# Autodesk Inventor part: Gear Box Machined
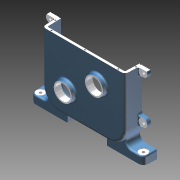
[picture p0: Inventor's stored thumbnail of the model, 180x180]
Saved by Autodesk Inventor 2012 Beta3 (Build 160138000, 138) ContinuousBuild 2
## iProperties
Created: 2008-05
Part Number: Gear Box Machined
Document SubType Name: Modeling
Designer: Thom Tremblay
Density: 2.71 g/cm^3
Material: Aluminum-6061
Mass: 2342.12 g
Surface Area: 1959.94 cm^2
Volume: 864.251 cm^3
Author: Thom Tremblay
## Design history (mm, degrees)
node "c8-12" dims "d0" = 10
workplane "Work Plane5"
split "Split4"
workplane "Work Plane1"
split "Split1"
workplane "Work Plane2"
split "Split2"
workplane "Work Plane3"
split "Split3"
sketch "Sketch2"
  geometry: L1 (-43.154, 195.566)-(-43.154, 43.154) reference; L2 (0, 0)-(152.426, 0) reference; L3 (195.579, 43.154)-(195.579, 195.566) reference; L4 (-44.932, 195.566)-(-44.932, 43.154); L5 (0, -1.778)-(152.426, -1.778); L6 (197.357, 43.154)-(197.357, 195.566); L7 (-48.107, 195.566)-(-48.107, 43.154); L8 (0, -4.953)-(152.426, -4.953); L9 (200.532, 43.154)-(200.532, 195.566); L10 (197.357, 195.566)-(200.532, 195.566); L11 (-48.107, 195.566)-(-44.932, 195.566); 2 further points; 2 other entities
  constraints: 16 end point, 8 parallel, 1 collinear, 1 perpendicular, 14 other
  dimensions: "d86" = 1.778 distance between parallel lines of L1 L4; "d87" = 3.175 distance of L7.start L4.start
extrude "Extrusion1" cut sketch "Sketch2" distance "d7" = 1.5875; taper "d8" = 0 deg
fillet "Fillet1" dims "d9" = 1.27
sketch "Sketch3"
  geometry: A1 r 12.342 centre (0, 9.804) between (-9.709, 17.424) and (0, -2.538) reference; A2 r 12.342 centre (0, -122.307) between (0, -109.965) and (0, -134.649) reference; A3 r 12.342 centre (99.06, -195.936) between (102.192, -207.874) and (111.402, -195.936) reference; A4 r 12.342 centre (185.42, -195.936) between (173.078, -195.936) and (182.288, -207.874) reference; A5 r 12.342 centre (284.48, -122.307) between (284.48, -134.649) and (284.48, -109.965) reference; A6 r 12.342 centre (284.48, 9.804) between (284.48, -2.538) and (294.189, 17.424) reference
hole "Hole4" sketch "Sketch3" at (0, 9.804), (0, -122.307), (99.06, -195.936), (185.42, -195.936), (284.48, -122.307), (284.48, 9.804) diameter "d37" = 8.4328; stored, may be unused: countersink angle "d41" = 82 deg, drill point angle "d43" = 118 deg; dims "d38" = 12.7, "d39" = 25.4, "d40" = 1.5875, "d42" = 19.05
sketch "Sketch4"
  geometry: L1 (-190.442, -18.372)-(-183.68, -30.3) reference; L2 (-255.6, 96.553)-(-248.837, 84.625) reference; L3 (-96.099, 8.151)-(-76.621, 8.151) reference; L4 (9.739, 8.151)-(-9.739, 8.151) reference; A1 r 12.7 centre (0, 0) between (9.739, 8.151) and (-9.739, 8.151) reference; A2 r 12.7 centre (-86.36, 0) between (-76.621, 8.151) and (-96.099, 8.151) reference; A3 r 12.7 centre (-196.361, -29.609) between (-183.68, -30.3) and (-190.442, -18.372) reference; A4 r 12.7 centre (-261.518, 85.317) between (-248.837, 84.625) and (-255.6, 96.553) reference
extrude "Extrusion2" cut sketch "Sketch4" stored distance "d44" = 1.5875; taper "d45" = 0 deg
workplane "Work Plane4"
hole "Hole5" diameter "d49" = 8.4328; stored, may be unused: countersink angle "d53" = 82 deg, drill point angle "d55" = 118 deg; dims "d47" = 25.4, "d48" = 25.4, "d50" = 12.7, "d51" = 25.4, "d52" = 1.5875, "d54" = 19.05
sketch "Sketch5"
  geometry: L1 (7.378, 0)-(0, 0) reference; A1 r 12.7 centre (0, -10.337) between (-12.382, -13.16) and (7.378, 0) reference; 2 further points; 1 other entity
  constraints: 2 other
extrude "Extrusion3" cut sketch "Sketch5" stored distance "d56" = 1.5875; taper "d57" = 0 deg
mirror "Mirror1"
hole "Hole6" diameter "d75" = 47; stored, may be unused: countersink angle "d79" = 82 deg, drill point angle "d81" = 118 deg; dims "d73" = 25.4, "d74" = 25.4, "d76" = 12.7, "d77" = 16.129, "d78" = 7.9502, "d80" = 19.05
chamfer "Chamfer2" distance "d82" = 1.27; stored, may be unused: second distance "d83" = 3.175, angle "d84" = 45 deg
sketch "Sketch7"
  geometry: L1 (233.368, 2.451)-(234.781, 42.926) reference; L2 (0, 0)-(230.829, 0) reference; L3 (-3.952, 42.926)-(-2.538, 2.451) reference; L4 (239.032, 55.493)-(237.175, 2.318); L5 (230.829, -3.81)-(0, -3.81); L6 (-6.346, 2.318)-(-8.203, 55.493); A1 r 2.54 centre (230.829, 2.54) between (230.829, 0) and (233.368, 2.451) reference; A2 r 2.54 centre (0, 2.54) between (-2.538, 2.451) and (0, 0) reference; A3 r 6.35 centre (230.829, 2.54) between (230.829, -3.81) and (237.175, 2.318); A4 r 6.35 centre (0, 2.54) between (-6.346, 2.318) and (0, -3.81); 5 further points
  constraints: 6 end point, 4 point on circle, 3 midpoint, 2 centre point, 2 point on line, 4 other
  dimensions: "d88" = 3.81 distance between parallel lines of L2 L5; "d89" = 101.6 distance of point (115.415, -3.81) point (217.015, -3.81); "d90" = 101.6 distance of point (13.815, -3.81) point (115.415, -3.81) (= d89)
hole "Hole8" sketch "Sketch7" at (115.415, -3.81), (217.015, -3.81), (13.815, -3.81), (-7.275, 28.906), (238.104, 28.906) diameter "d91" = 4.3434; stored, may be unused: countersink angle "d95" = 82 deg, drill point angle "d97" = 118 deg; dims "d92" = 8.89, "d93" = 16.129, "d94" = 7.9502, "d96" = 12.7
body "Solid1"
hole "Hole7" diameter "d66" = 47 (= d75); stored, may be unused: countersink angle "d70" = 82 deg, drill point angle "d72" = 118 deg; dims "d64" = 25.4, "d65" = 25.4, "d67" = 12.7, "d68" = 16.129, "d69" = 7.9502, "d71" = 19.05
tag "TaggingFeature2"
node "Projected Loop1"
node "Projected Loop2"
node "Projected Loop3"
node "Projected Loop4"
node "Projected Loop5"
feature "Solid1::c8-12" dims "d0" = 10
other parameters: "d1" = 203.2, "d3" = -63.5, "d46" = -22.098, "d85" = 0.254
